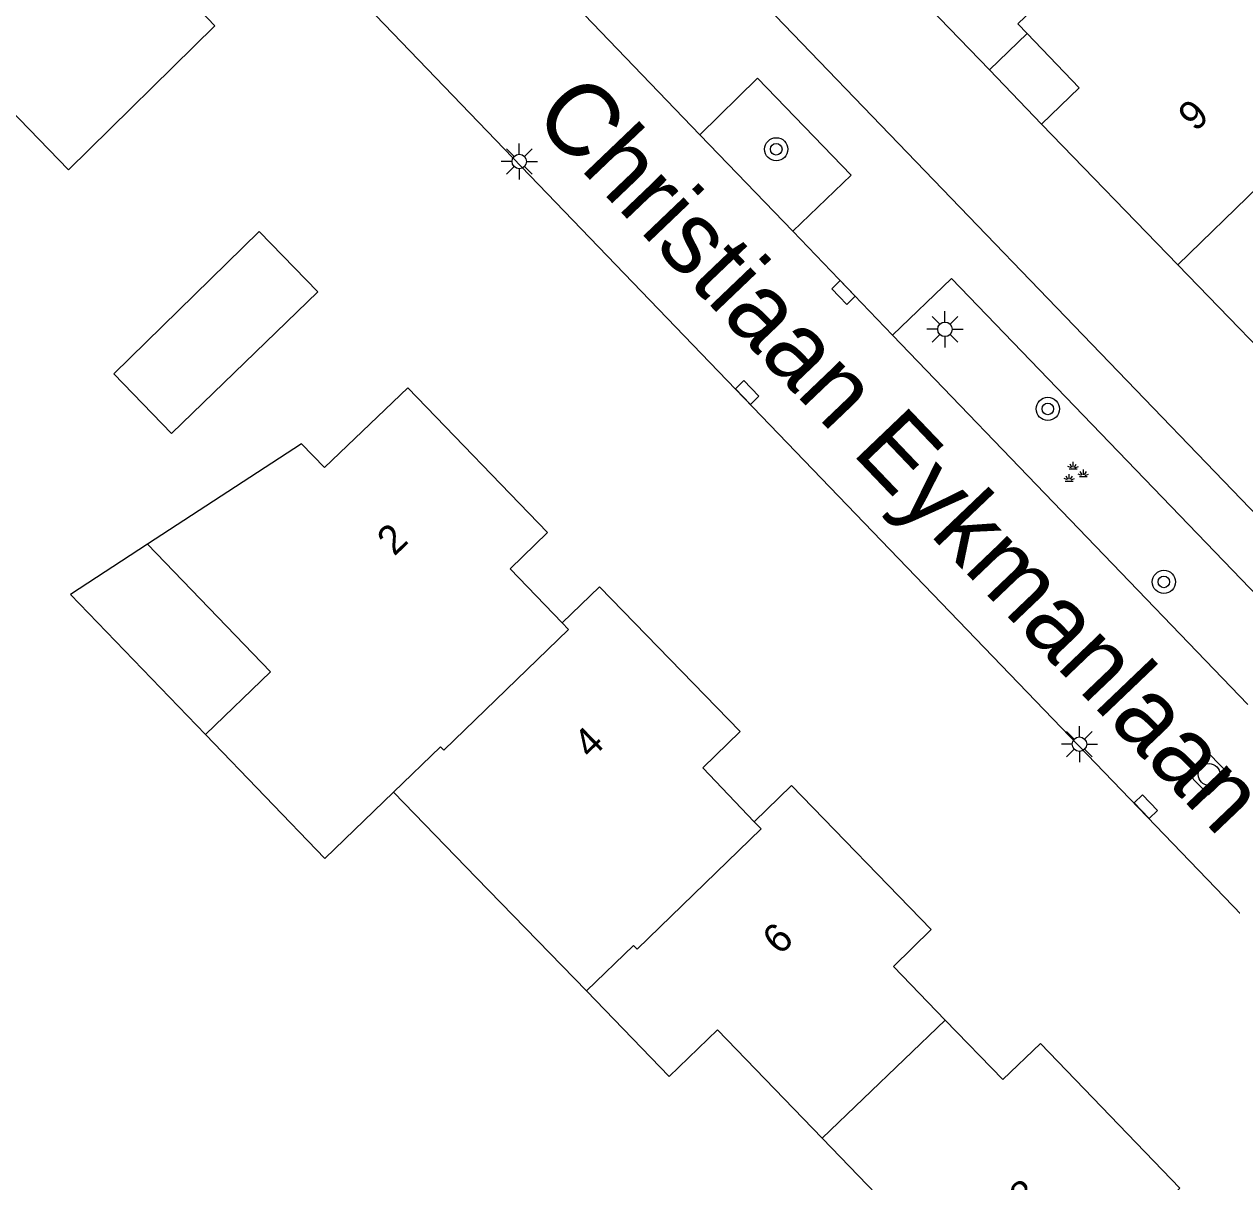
# Model space of a CAD drawing. Extents: x 137999 to 141000, y 397500 to 400501.
# Drawn here: x 138644.23 to 138685.92, y 399538.91 to 399578.88 of the extents above; entities that cross this region are included whole.
import ezdxf

# ---------------------------------------------------------------- set-up
doc = ezdxf.new("R2010")
doc.units = 0
for name, color, linetype in [('gg-anno-huisnummerreeks BGT', 7, 'Continuous'), ('gg-anno-openbare ruimte label', 7, 'Continuous'), ('gg-bbg-bijgebouw', 7, 'Continuous'), ('gg-bbg-gedigitaliseerde bebouwing', 7, 'Continuous'), ('gg-bbg-gedigitaliseerde bijgebouw', 7, 'Continuous'), ('gg-bbg-hoofdgebouw', 7, 'Continuous'), ('gg-bbg-luifel en loopbrug', 7, 'Continuous'), ('gg-bbg-tussenscheiding', 7, 'Continuous'), ('gg-knt-verharding', 7, 'Continuous'), ('gt-symb-boom', 7, 'Continuous'), ('gt-symb-groenvak', 7, 'Continuous'), ('gt-symb-kolk', 7, 'Continuous'), ('gt-symb-lichtmast', 7, 'Continuous'), ('gt-symb-rioolschacht', 7, 'Continuous')]:
    doc.layers.add(name, color=color, linetype=linetype)

# ---------------------------------------------------------------- blocks, each defined once
blk = doc.blocks.new('gt0-KOLK')
at = {"layer": 'gt-symb-kolk'}
blk.add_lwpolyline([(0, 0), (0.375, 0), (0.375, 0.4), (-0.375, 0.4), (-0.375, 0), (0, 0)], dxfattribs=at)
blk = doc.blocks.new('gt0-RS')
at = {"layer": 'gt-symb-rioolschacht'}
blk.add_lwpolyline([(-0.5, -0.5), (0.5, -0.5), (0.5, 0.5), (-0.5, 0.5)], close=True, dxfattribs=at)
blk.add_circle((0, 0), 0.375, dxfattribs=at)
blk = doc.blocks.new('gt0-LMAST')
at = {"layer": 'gt-symb-lichtmast'}
for p, q in [((-0.182, 0.173), (-0.447, 0.438)), ((-0.005, 0.246), (-0.005, 0.621)), ((0.172, 0.173), (0.437, 0.438)), ((-0.255, -0.004), (-0.63, -0.004)), ((-0.182, -0.181), (-0.447, -0.446)), ((-0.005, -0.254), (-0.005, -0.629)), ((0.437, -0.446), (0.172, -0.181)), ((0.245, -0.004), (0.62, -0.004))]:
    blk.add_line(p, q, dxfattribs=at)
blk.add_circle((-0.005, -0.004), 0.25, dxfattribs=at)
blk = doc.blocks.new('gt0-BOOM')
at = {"layer": 'gt-symb-boom'}
for radius in [0.4, 0.2]:
    blk.add_circle((0, 0), radius, dxfattribs=at)
blk = doc.blocks.new('gt0-GRVAK')
at = {"layer": 'gt-symb-groenvak'}
for p, q in [((-0.11, 0.189), (-0.228, 0.24)), ((-0.182, 0.153), (0.088, 0.153)), ((-0.091, 0.211), (-0.156, 0.322)), ((-0.047, 0.214), (-0.047, 0.393)), ((-0.004, 0.211), (0.061, 0.322)), ((0.015, 0.189), (0.133, 0.24)), ((0.262, -0.052), (0.197, 0.059)), ((0.305, -0.049), (0.305, 0.13)), ((0.349, -0.052), (0.414, 0.059)), ((-0.245, -0.228), (-0.363, -0.177)), ((-0.318, -0.264), (-0.047, -0.264)), ((-0.226, -0.206), (-0.291, -0.095)), ((-0.183, -0.203), (-0.183, -0.024)), ((-0.139, -0.206), (-0.074, -0.095)), ((-0.12, -0.228), (-0.002, -0.177)), ((0.243, -0.074), (0.125, -0.023)), ((0.17, -0.11), (0.441, -0.11)), ((0.368, -0.074), (0.486, -0.023))]:
    blk.add_line(p, q, dxfattribs=at)

msp = doc.modelspace()

# ---------------------------------------------------------------- linework, layer by layer
at = {"layer": 'gg-bbg-bijgebouw'}
msp.add_line((138654.36, 399569.64), (138652.344, 399571.725), dxfattribs=at)
at = {"layer": 'gg-bbg-gedigitaliseerde bebouwing'}
for p, q in [((138653.797, 399564.394), (138648.482, 399560.927)), ((138656.978, 399552.364), (138659.842, 399549.402)), ((138659.842, 399549.402), (138663.636, 399545.501))]:
    msp.add_line(p, q, dxfattribs=at)
for points in [[(138650.485, 399554.354), (138652.731, 399556.519), (138648.482, 399560.927)], [(138650.485, 399554.354), (138654.607, 399550.078), (138656.978, 399552.364)], [(138663.636, 399545.501), (138666.49, 399542.549), (138668.155, 399544.158), (138671.776, 399540.412)], [(138671.776, 399540.412), (138675.828, 399536.22), (138674.171, 399534.618), (138677.01, 399531.681), (138678.641, 399533.258)]]:
    msp.add_lwpolyline(points, dxfattribs=at)
at = {"layer": 'gg-bbg-gedigitaliseerde bijgebouw'}
msp.add_line((138652.344, 399571.725), (138647.326, 399566.804), dxfattribs=at)
msp.add_lwpolyline([(138654.36, 399569.64), (138649.314, 399564.748), (138647.326, 399566.804)], dxfattribs=at)
at = {"layer": 'gg-bbg-hoofdgebouw'}
for p, q in [((138677.55, 399577.31), (138672.8, 399582.23)), ((138678.85, 399578.56), (138677.55, 399577.31)), ((138684.051, 399570.573), (138679.35, 399575.431))]:
    msp.add_line(p, q, dxfattribs=at)
for points in [[(138638.77, 399575.927), (138641.341, 399578.416), (138645.758, 399573.853), (138650.811, 399578.83), (138645.641, 399584.235), (138642.855, 399581.544), (138637.71, 399586.87)], [(138679.35, 399575.431), (138680.65, 399576.69), (138678.85, 399578.56)], [(138690.753, 399567.925), (138688.64, 399565.83), (138684.051, 399570.573)], [(138657.47, 399566.33), (138654.591, 399563.57), (138653.797, 399564.394)], [(138662.8, 399558.21), (138661, 399560.08), (138662.29, 399561.33), (138657.47, 399566.33)], [(138669.43, 399551.34), (138667.65, 399553.2), (138668.94, 399554.46), (138664.09, 399559.46), (138662.8, 399558.21)], [(138676.025, 399544.494), (138674.24, 399546.34), (138675.54, 399547.62), (138670.72, 399552.59), (138669.43, 399551.34)], [(138682.83, 399537.44), (138684.12, 399538.69), (138679.31, 399543.69), (138678.01, 399542.44), (138676.025, 399544.494)]]:
    msp.add_lwpolyline(points, dxfattribs=at)
at = {"layer": 'gg-bbg-luifel en loopbrug'}
for p, q in [((138677.55, 399577.31), (138679.35, 399575.431)), ((138648.482, 399560.927), (138645.821, 399559.192)), ((138645.821, 399559.192), (138650.485, 399554.354))]:
    msp.add_line(p, q, dxfattribs=at)
at = {"layer": 'gg-bbg-tussenscheiding'}
for p, q in [((138691.234, 399577.566), (138684.051, 399570.573)), ((138676.025, 399544.494), (138671.776, 399540.412))]:
    msp.add_line(p, q, dxfattribs=at)
for points in [[(138684.622, 399584.393), (138683.138, 399582.958), (138682.958, 399583.146), (138678.523, 399578.898), (138678.85, 399578.56)], [(138662.8, 399558.21), (138663.021, 399557.982), (138658.713, 399553.81), (138658.597, 399553.929), (138656.978, 399552.364)], [(138663.636, 399545.501), (138665.26, 399547.071), (138665.39, 399546.94), (138669.666, 399551.095), (138669.43, 399551.34)]]:
    msp.add_lwpolyline(points, dxfattribs=at)
at = {"layer": 'gg-knt-verharding'}
for p, q in [((138646.5, 399603.75), (138689.87, 399558.7)), ((138639.352, 399596.873), (138706.182, 399527.423)), ((138662.446, 399580.376), (138667.555, 399575.06)), ((138667.555, 399575.06), (138670.756, 399571.73)), ((138670.756, 399571.73), (138674.203, 399568.143)), ((138676.235, 399570.096), (138674.203, 399568.143)), ((138688.5, 399557.36), (138676.235, 399570.096)), ((138674.203, 399568.143), (138686.462, 399555.39))]:
    msp.add_line(p, q, dxfattribs=at)
msp.add_lwpolyline([(138667.555, 399575.06), (138669.538, 399577.016), (138672.776, 399573.671), (138670.756, 399571.73)], dxfattribs=at)

# ---------------------------------------------------------------- block references
at = {"layer": 'gt-symb-boom'}
for p in [(138670.187, 399574.564), (138679.563, 399565.598), (138683.569, 399559.625)]:
    msp.add_blockref('gt0-BOOM', p, dxfattribs=at)
at = {"layer": 'gt-symb-groenvak'}
msp.add_blockref('gt0-GRVAK', (138680.485, 399563.373), dxfattribs=at)
at = {"layer": 'gt-symb-kolk'}
for p, rotation in [((138672.364, 399569.479), -46.13442162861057), ((138669.036, 399566.026), -46.13442163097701), ((138682.801, 399551.726), -46.13442163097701)]:
    msp.add_blockref('gt0-KOLK', p, dxfattribs=dict(at, rotation=rotation))
at = {"layer": 'gt-symb-lichtmast'}
for p in [(138661.323, 399574.145), (138676.017, 399568.35), (138680.66, 399554.026)]:
    msp.add_blockref('gt0-LMAST', p, dxfattribs=at)
at = {"layer": 'gt-symb-rioolschacht', "rotation": -46.13442163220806}
msp.add_blockref('gt0-RS', (138685.129, 399552.974), dxfattribs=at)

# ---------------------------------------------------------------- texts
at = {"layer": 'gg-anno-huisnummerreeks BGT'}
for s, rotation, p in [('9', 44, (138684.659, 399575.138)), ('2', 43.9, (138657.003, 399560.491)), ('4', 44.1, (138663.782, 399553.474)), ('6', 44.1, (138670.312, 399546.707)), ('8', 43.9, (138678.834, 399537.854))]:
    msp.add_text(s, height=1, rotation=rotation, dxfattribs=at).set_placement(p)
at = {"layer": 'gg-anno-openbare ruimte label'}
msp.add_text('Christiaan Eykmanlaan', height=2.5, rotation=313.7, dxfattribs=at).set_placement((138661.723, 399575.632))

doc.saveas('drawing.dxf')
